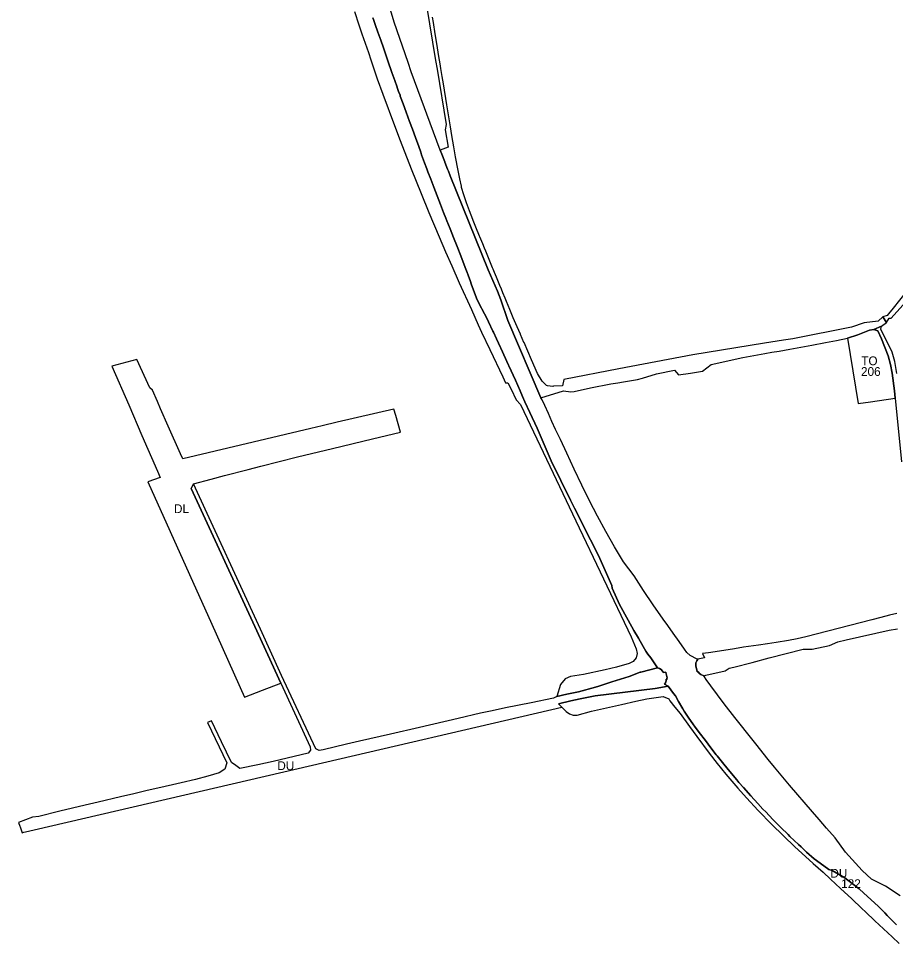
# Model space of a CAD drawing. Extents: x -521047 to -518054, y -1194945 to -1189555.
# Drawn here: x -521047 to -520050, y -1192673 to -1191621 of the extents above; entities that cross this region are included whole.
import ezdxf

# ---------------------------------------------------------------- set-up
doc = ezdxf.new("R2010")
doc.units = 0
for name, color, linetype in [('90310013', 7, 'Continuous'), ('90310023', 7, 'Continuous'), ('90320013', 7, 'Continuous'), ('90340013', 7, 'Continuous'), ('90430023', 7, 'Continuous'), ('90450013', 7, 'Continuous'), ('ID_navrh', 7, 'Continuous')]:
    doc.layers.add(name, color=color, linetype=linetype)

msp = doc.modelspace()

# ---------------------------------------------------------------- linework, layer by layer
at = {"layer": '90310013'}
for points in [[(-520583.24, -1191606.18), (-520572.92, -1191668.76), (-520571.31, -1191678.64), (-520560.94, -1191741.4), (-520562, -1191747.31), (-520558.71, -1191767.21), (-520567.63, -1191770.59), (-520565.86, -1191775.32), (-520562.43, -1191784.06), (-520562.29, -1191784.41), (-520559.25, -1191792.33), (-520558.35, -1191794.67), (-520556.42, -1191799.88), (-520513.1, -1191906.77), (-520502.57, -1191931.05), (-520498.81, -1191940.91), (-520490.89, -1191964.3), (-520453.11, -1192052.05), (-520427.58, -1192044.36), (-520419.12, -1192045.34), (-520415.23, -1192044.95), (-520396.61, -1192040.92), (-520373.61, -1192036.43), (-520365.78, -1192035.12), (-520359.07, -1192034), (-520343.38, -1192031.33), (-520337.55, -1192029.72), (-520321.68, -1192025.09), (-520301.24, -1192020.66), (-520296.64, -1192026.13), (-520282.86, -1192024.02), (-520269.44, -1192022.05), (-520259.31, -1192014.22), (-520223.56, -1192006.45), (-520211.03, -1192004.19), (-520198.5, -1192001.91), (-520190.36, -1192000.43), (-520182.23, -1191998.96), (-520169.8, -1191996.69), (-520157.4, -1191994.44), (-520144.97, -1191992.17), (-520129.2, -1191989.31), (-520116.89, -1191987.05), (-520104.53, -1191984.27), (-520092.41, -1191980.61), (-520079.34, -1191975.35), (-520074.25, -1191974.62), (-520065.72, -1191970.89), (-520060.15, -1191966.67), (-520064.17, -1191960.26), (-520069.51, -1191964.99), (-520085.46, -1191967.04), (-520099.84, -1191971.93), (-520166.67, -1191985.2), (-520177.25, -1191986.81), (-520198.94, -1191990.1), (-520280.31, -1192003.2), (-520364.5, -1192019.1), (-520426.95, -1192031.34)], [(-520426.95, -1192031.34), (-520428.58, -1192038.61), (-520438.66, -1192038.99), (-520439.75, -1192039.45), (-520445.83, -1192038.53), (-520446.9, -1192038.37), (-520451.84, -1192033.1), (-520456.96, -1192024.37), (-520463.71, -1192009.09), (-520472.36, -1191989.33), (-520472.43, -1191989.16), (-520476.27, -1191980.29), (-520476.54, -1191979.67), (-520480.14, -1191971.36), (-520484.6, -1191961.08), (-520488.52, -1191951.69), (-520492.29, -1191942.67), (-520492.35, -1191942.53), (-520493.89, -1191938.79), (-520496.32, -1191932.89), (-520498, -1191928.82), (-520499.82, -1191924.41), (-520501.41, -1191920.55), (-520503.68, -1191914.99), (-520505.77, -1191909.89), (-520507.4, -1191905.91), (-520508.05, -1191904.38), (-520515.15, -1191887.48), (-520515.96, -1191885.49), (-520517.43, -1191881.88), (-520519.36, -1191877.12), (-520522.68, -1191868.97), (-520522.92, -1191868.36), (-520527.05, -1191858.16), (-520530.18, -1191850.44), (-520530.55, -1191849.48), (-520534.33, -1191839.76), (-520537.93, -1191830.32), (-520540.91, -1191821.42), (-520543.32, -1191813.06), (-520543.6, -1191811.69), (-520545.36, -1191803.05), (-520547.27, -1191793.71), (-520550.3, -1191778.29), (-520552.16, -1191767), (-520554.32, -1191753.79), (-520555.95, -1191744), (-520557.81, -1191732.77), (-520560.08, -1191719.1), (-520564, -1191695.24), (-520565.37, -1191686.86), (-520566.91, -1191677.66), (-520567.79, -1191672.26), (-520569.19, -1191663.93), (-520571.57, -1191649.5), (-520573.38, -1191638.42), (-520575.51, -1191625.38), (-520576.48, -1191619.53)], [(-520048.04, -1192024.54), (-520050.49, -1192010.79), (-520053.59, -1192000.14), (-520066.59, -1191973.96), (-520065.72, -1191970.89), (-520074.25, -1191974.62), (-520069.93, -1191975.99), (-520065.48, -1191985.04), (-520058.25, -1192004.27), (-520055.59, -1192014.2), (-520053.58, -1192024.28), (-520050.85, -1192044.4), (-520050, -1192052.77), (-520042.86, -1192124.96)], [(-520308.29, -1192379.91), (-520312.6, -1192377.77), (-520311.52, -1192376.37), (-520310.68, -1192374.15), (-520310.56, -1192372.14), (-520309.5, -1192371.9), (-520309.71, -1192370.96), (-520309.59, -1192370.62), (-520310.97, -1192364.44), (-520311.06, -1192364.05), (-520313.84, -1192364.68), (-520314.84, -1192362.92), (-520316.29, -1192361.16), (-520318.16, -1192359.98), (-520320.4, -1192359.14), (-520339.38, -1192363.97), (-520340.17, -1192364.16), (-520352.73, -1192368.93), (-520372.47, -1192375.28), (-520387.37, -1192380.02), (-520390.99, -1192381.17), (-520410.3, -1192386.31), (-520423.63, -1192389.27), (-520435.18, -1192391.83), (-520438.72, -1192393.79), (-520464.05, -1192398.85), (-520493.5, -1192404.76), (-520508.74, -1192407.91), (-520521.69, -1192410.69), (-520547.23, -1192416.63), (-520591.42, -1192426.87), (-520624.25, -1192434.52), (-520659.49, -1192442.68), (-520674.16, -1192446.1), (-520700.9, -1192452.29), (-520705.38, -1192453.34), (-520709.22, -1192451.33), (-520748.17, -1192367.77), (-520772.3, -1192315.26), (-520848.21, -1192150.07), (-520851.18, -1192155.31), (-520778.66, -1192312.37), (-520749.03, -1192376.55), (-520715.58, -1192448.99), (-520715.38, -1192452.8), (-520717.93, -1192456.26), (-520757.59, -1192465.66), (-520775.03, -1192469.66), (-520795.54, -1192473.81), (-520800.34, -1192470.38), (-520805.14, -1192466.95), (-520816.49, -1192443.18), (-520827.84, -1192419.41), (-520832.42, -1192421.41), (-520810.52, -1192467.28), (-520812.86, -1192474.26), (-520819, -1192478.55), (-520831.91, -1192482.32), (-520846.11, -1192486.03), (-520862.36, -1192489.81), (-520867.3, -1192490.96), (-520885.36, -1192495.15), (-520901.21, -1192498.82), (-520916.4, -1192502.38), (-520931.25, -1192505.82), (-520956.94, -1192511.77), (-520971.48, -1192515.16), (-521000.32, -1192522.3), (-521024.31, -1192528.23), (-521031.5, -1192528.93), (-521047.48, -1192534.92), (-521045.8, -1192539.12), (-521045.42, -1192540.08), (-521043.45, -1192546.66), (-521041.54, -1192546.21), (-521039.64, -1192545.77), (-521034.64, -1192544.61), (-521029.64, -1192543.45), (-520729.45, -1192473.76), (-520429.27, -1192404.08), (-520433.25, -1192400.13), (-520419.21, -1192396.83), (-520408.52, -1192394.32), (-520391.27, -1192391.06), (-520323, -1192382.65), (-520308.29, -1192379.91)], [(-520048.15, -1192297.25), (-520056.72, -1192299.47), (-520066.54, -1192302), (-520076.52, -1192304.58), (-520151.67, -1192323.97), (-520161.54, -1192326.38), (-520171.64, -1192328.13), (-520185.37, -1192330.24), (-520195.42, -1192331.76), (-520205.45, -1192333.29), (-520222.7, -1192335.85), (-520232.72, -1192337.5), (-520254.9, -1192340.88), (-520262.42, -1192342.12), (-520269.2, -1192343.04), (-520267.02, -1192347.71), (-520274.54, -1192349.23), (-520275.84, -1192351.17), (-520276.91, -1192353.53), (-520277.02, -1192356.01), (-520276.82, -1192356.91), (-520275.37, -1192363.33), (-520275.24, -1192363.9), (-520274.14, -1192363.66), (-520272.78, -1192365.55), (-520271.03, -1192366.84), (-520267.65, -1192368.23)], [(-520267.65, -1192368.23), (-520265.64, -1192367.66), (-520243.36, -1192362.72), (-520238.84, -1192359.64), (-520233.56, -1192358.34), (-520212.74, -1192353.2), (-520193.4, -1192348.01), (-520174.07, -1192342.77), (-520154.82, -1192337.98), (-520144.55, -1192338.08), (-520124.86, -1192333.87), (-520115.51, -1192329.52), (-520105.95, -1192327.26), (-520057.05, -1192316.46), (-520047.46, -1192314.76)]]:
    msp.add_lwpolyline(points, dxfattribs=at)
at = {"layer": '90310023'}
for points in [[(-520665.33, -1191613.04), (-520660.4, -1191628.12), (-520656.86, -1191638.41), (-520649.42, -1191659.64), (-520646.67, -1191667.99), (-520639.25, -1191689.54), (-520632.82, -1191707.09), (-520619.58, -1191742.71), (-520613.34, -1191759.5), (-520600.61, -1191791.87), (-520589.45, -1191820.06), (-520580.78, -1191841.33), (-520568.92, -1191869.32), (-520561.8, -1191886.19), (-520554.58, -1191902.23), (-520545.99, -1191921.37), (-520532.26, -1191951.92), (-520524.4, -1191969.39), (-520520.62, -1191977.39), (-520511.32, -1191997.09), (-520496.63, -1192028.24), (-520493.41, -1192035.03), (-520490.69, -1192035.01), (-520487.08, -1192042.46), (-520481.41, -1192054.32), (-520476.52, -1192059.92), (-520413.24, -1192192.22), (-520350.34, -1192323.78), (-520344.77, -1192337.74), (-520343.61, -1192342.88), (-520344.8, -1192347.99), (-520348.08, -1192352.07), (-520352.85, -1192354.32), (-520367.27, -1192358.55), (-520379.97, -1192361.36), (-520404.73, -1192366.86), (-520419.59, -1192369.13), (-520425.51, -1192371.59), (-520430.97, -1192378.16), (-520435.18, -1192391.83), (-520423.63, -1192389.27), (-520410.3, -1192386.31), (-520390.99, -1192381.17), (-520387.37, -1192380.02), (-520372.47, -1192375.28), (-520352.73, -1192368.93), (-520340.17, -1192364.16), (-520339.38, -1192363.97), (-520320.4, -1192359.14), (-520325.1, -1192352.46), (-520328.24, -1192347.97), (-520331.36, -1192343.58), (-520333.65, -1192340.33), (-520336.81, -1192334.84), (-520342.29, -1192325.3), (-520347.31, -1192316.58), (-520353.88, -1192305.15), (-520363.69, -1192287.06), (-520371.94, -1192268.45), (-520372.29, -1192265.77), (-520387.63, -1192231.6), (-520396.88, -1192213.72), (-520414.93, -1192177.76), (-520419.64, -1192168.56), (-520441.55, -1192123.72), (-520449.56, -1192105.3), (-520457.37, -1192086.83), (-520465.86, -1192068.71), (-520471.3, -1192056.68), (-520474.06, -1192050.59), (-520476.86, -1192044.07), (-520482.01, -1192032.05), (-520489.78, -1192015.99), (-520490.14, -1192015.17), (-520498.74, -1191995.62), (-520499.13, -1191994.79), (-520503.53, -1191985.28), (-520507.16, -1191977.44), (-520507.66, -1191976.43), (-520512.79, -1191965.9), (-520515.96, -1191959.4), (-520517.18, -1191956.82), (-520523.93, -1191944.46), (-520526.29, -1191938.72), (-520532.31, -1191922.75), (-520533.39, -1191919.77), (-520535.87, -1191912.92), (-520537.01, -1191909.76), (-520539.14, -1191903.88), (-520544.3, -1191890.84), (-520548.49, -1191880.24), (-520552.5, -1191870.05), (-520556.46, -1191860.17), (-520560.11, -1191851.11), (-520561.36, -1191848.01), (-520563.85, -1191841.56), (-520567.46, -1191832.2), (-520571.18, -1191822.61), (-520574.96, -1191812.85), (-520578.48, -1191803.63), (-520581.71, -1191795.12), (-520582.94, -1191791.88), (-520585.49, -1191784.87), (-520588.8, -1191775.76), (-520589.8, -1191773.03), (-520592.13, -1191766.51), (-520595.79, -1191756.32), (-520599.31, -1191746.66), (-520602.48, -1191737.99), (-520606.37, -1191727.43), (-520609.95, -1191717.76), (-520613.08, -1191709.13), (-520613.42, -1191708.19), (-520614.97, -1191703.91), (-520616.56, -1191699.54), (-520616.79, -1191698.9), (-520619.43, -1191691.52), (-520622.73, -1191682.3), (-520623.96, -1191678.84), (-520626.06, -1191672.54), (-520629.16, -1191663.22), (-520629.49, -1191662.22), (-520632.32, -1191654.19), (-520635.33, -1191645.63), (-520638.56, -1191636.54), (-520641.71, -1191627.72), (-520643.73, -1191622.06), (-520644.52, -1191620)], [(-520308.29, -1192379.91), (-520323, -1192382.65), (-520391.27, -1192391.06), (-520408.52, -1192394.32), (-520419.21, -1192396.83), (-520433.25, -1192400.13), (-520429.27, -1192404.08), (-520424.5, -1192408.81), (-520420.44, -1192411.62), (-520416.34, -1192412.93), (-520412.04, -1192413.12), (-520395.48, -1192408.42), (-520361.57, -1192400.9), (-520345.17, -1192397.26), (-520332.75, -1192394.51), (-520314.08, -1192391.89), (-520307.78, -1192394.28), (-520306.33, -1192396.84), (-520300.6, -1192403.76), (-520294.74, -1192411.1), (-520284.01, -1192425.9), (-520275.92, -1192437.11), (-520261.71, -1192456.26), (-520252.63, -1192468), (-520242.91, -1192479.92), (-520229.16, -1192496.14), (-520219.35, -1192507.19), (-520206.14, -1192521.43), (-520190.54, -1192537.37), (-520164.14, -1192562.58), (-520156.21, -1192570), (-520143.43, -1192581.71), (-520132.06, -1192591.63), (-520123.66, -1192599.39), (-520112.32, -1192610.16), (-520099.47, -1192621.84), (-520088.02, -1192632.83), (-520083.77, -1192636.81), (-520073.19, -1192646.74), (-520053.58, -1192665.11), (-520045.5, -1192672.63)], [(-520048.69, -1192651.55), (-520055.38, -1192644.58), (-520059.17, -1192640.62), (-520061.83, -1192637.85), (-520068.05, -1192631.68), (-520069.09, -1192630.69), (-520077.92, -1192622.6), (-520085.81, -1192615.47), (-520091.18, -1192610.64), (-520094.08, -1192608.35), (-520107.21, -1192597.98), (-520121.95, -1192589.69), (-520125.41, -1192588.44), (-520139.68, -1192578.29), (-520142.13, -1192576.55), (-520150.82, -1192568.64), (-520157.19, -1192562.84), (-520159.9, -1192560.25), (-520169.79, -1192550.8), (-520171.93, -1192548.76), (-520180.03, -1192540.77), (-520186.45, -1192534.45), (-520189.15, -1192531.64), (-520197.42, -1192523.04), (-520200.54, -1192519.8), (-520206.32, -1192513.55), (-520214.38, -1192504.82), (-520222.74, -1192495.39), (-520227.93, -1192489.55), (-520230.36, -1192486.59), (-520238.03, -1192477.24), (-520245.01, -1192468.75), (-520252.72, -1192459.36), (-520253.78, -1192458.07), (-520259.81, -1192450.1), (-520266.04, -1192441.85), (-520273.06, -1192432.56), (-520278.33, -1192425.59), (-520279.48, -1192423.96), (-520285.5, -1192415.41), (-520290.27, -1192408.65), (-520291.84, -1192405.87), (-520296.67, -1192397.37), (-520300.19, -1192391.16), (-520302.3, -1192388.23), (-520308.29, -1192379.91)]]:
    msp.add_lwpolyline(points, dxfattribs=at)
at = {"layer": '90320013'}
for points in [[(-520044.56, -1192618.55), (-520061.16, -1192607.27), (-520076.96, -1192599.48), (-520087.56, -1192589.6), (-520106.61, -1192568.96), (-520118.39, -1192552.66), (-520128.18, -1192541.53), (-520136.69, -1192531.64), (-520144.14, -1192523.08), (-520170.22, -1192492.58), (-520187.51, -1192472.01), (-520194.58, -1192463.28), (-520208.64, -1192445.57), (-520211.73, -1192441.71), (-520232.33, -1192415.78), (-520244.47, -1192400.09), (-520259.75, -1192379.49), (-520264.96, -1192372.31), (-520267.03, -1192369.46), (-520267.65, -1192368.23), (-520271.03, -1192366.84), (-520272.78, -1192365.55), (-520274.14, -1192363.66), (-520275.24, -1192363.9), (-520275.37, -1192363.33), (-520276.82, -1192356.91), (-520277.02, -1192356.01), (-520276.91, -1192353.53), (-520275.84, -1192351.17), (-520274.54, -1192349.23), (-520275.44, -1192349.46), (-520283.19, -1192345.02), (-520287.05, -1192341.84), (-520289.68, -1192338.14), (-520295.99, -1192329.24), (-520302.69, -1192319.77), (-520308.83, -1192311.12), (-520313.94, -1192303.92), (-520325.37, -1192287.72), (-520336.34, -1192271.22), (-520347.07, -1192254.47), (-520359.31, -1192238.71), (-520369.38, -1192221.59), (-520379.14, -1192204.29), (-520388.67, -1192186.84), (-520397.97, -1192169.26), (-520406.75, -1192151.4), (-520415.17, -1192133.35), (-520423.57, -1192115.27), (-520430.99, -1192099.66), (-520436.41, -1192088.25), (-520440.7, -1192079.25), (-520444.67, -1192070.07), (-520448.65, -1192060.89), (-520451.85, -1192054.55), (-520452.5, -1192053.26), (-520453.11, -1192052.05), (-520490.89, -1191964.3), (-520498.81, -1191940.91), (-520502.57, -1191931.05), (-520513.1, -1191906.77), (-520556.42, -1191799.88), (-520558.35, -1191794.67), (-520559.25, -1191792.33), (-520562.29, -1191784.41), (-520562.43, -1191784.06), (-520565.86, -1191775.32), (-520567.63, -1191770.59), (-520600.77, -1191681.45), (-520604.04, -1191671.07), (-520620.11, -1191625.25), (-520624.44, -1191610.86)], [(-520644.52, -1191620), (-520643.73, -1191622.06), (-520641.71, -1191627.72), (-520638.56, -1191636.54), (-520635.33, -1191645.63), (-520632.32, -1191654.19), (-520629.49, -1191662.22), (-520629.16, -1191663.22), (-520626.06, -1191672.54), (-520623.96, -1191678.84), (-520622.73, -1191682.3), (-520619.43, -1191691.52), (-520616.79, -1191698.9), (-520616.56, -1191699.54), (-520614.97, -1191703.91), (-520613.42, -1191708.19), (-520613.08, -1191709.13), (-520609.95, -1191717.76), (-520606.37, -1191727.43), (-520602.48, -1191737.99), (-520599.31, -1191746.66), (-520595.79, -1191756.32), (-520592.13, -1191766.51), (-520589.8, -1191773.03), (-520588.8, -1191775.76), (-520585.49, -1191784.87), (-520582.94, -1191791.88), (-520581.71, -1191795.12), (-520578.48, -1191803.63), (-520574.96, -1191812.85), (-520571.18, -1191822.61), (-520567.46, -1191832.2), (-520563.85, -1191841.56), (-520561.36, -1191848.01), (-520560.11, -1191851.11), (-520556.46, -1191860.17), (-520552.5, -1191870.05), (-520548.49, -1191880.24), (-520544.3, -1191890.84), (-520539.14, -1191903.88), (-520537.01, -1191909.76), (-520535.87, -1191912.92), (-520533.39, -1191919.77), (-520532.31, -1191922.75), (-520526.29, -1191938.72), (-520523.93, -1191944.46), (-520517.18, -1191956.82), (-520515.96, -1191959.4), (-520512.79, -1191965.9), (-520507.66, -1191976.43), (-520507.16, -1191977.44), (-520503.53, -1191985.28), (-520499.13, -1191994.79), (-520498.74, -1191995.62), (-520490.14, -1192015.17), (-520489.78, -1192015.99), (-520482.01, -1192032.05), (-520476.86, -1192044.07), (-520474.06, -1192050.59), (-520471.3, -1192056.68), (-520465.86, -1192068.71), (-520457.37, -1192086.83), (-520449.56, -1192105.3), (-520441.55, -1192123.72), (-520419.64, -1192168.56), (-520414.93, -1192177.76), (-520396.88, -1192213.72), (-520387.63, -1192231.6), (-520372.29, -1192265.77), (-520371.94, -1192268.45), (-520363.69, -1192287.06), (-520353.88, -1192305.15), (-520347.31, -1192316.58), (-520342.29, -1192325.3), (-520336.81, -1192334.84), (-520333.65, -1192340.33), (-520331.36, -1192343.58), (-520328.24, -1192347.97), (-520325.1, -1192352.46), (-520320.4, -1192359.14), (-520318.16, -1192359.98), (-520316.29, -1192361.16), (-520314.84, -1192362.92), (-520313.84, -1192364.68), (-520311.06, -1192364.05), (-520310.97, -1192364.44), (-520309.59, -1192370.62), (-520309.71, -1192370.96), (-520309.5, -1192371.9), (-520310.56, -1192372.14), (-520310.68, -1192374.15), (-520311.52, -1192376.37), (-520312.6, -1192377.77), (-520308.29, -1192379.91), (-520302.3, -1192388.23), (-520300.19, -1192391.16), (-520296.67, -1192397.37), (-520291.84, -1192405.87), (-520290.27, -1192408.65), (-520285.5, -1192415.41), (-520279.48, -1192423.96), (-520278.33, -1192425.59), (-520273.06, -1192432.56), (-520266.04, -1192441.85), (-520259.81, -1192450.1), (-520253.78, -1192458.07), (-520252.72, -1192459.36), (-520245.01, -1192468.75), (-520238.03, -1192477.24), (-520230.36, -1192486.59), (-520227.93, -1192489.55), (-520222.74, -1192495.39), (-520214.38, -1192504.82), (-520206.32, -1192513.55), (-520200.54, -1192519.8), (-520197.42, -1192523.04), (-520189.15, -1192531.64), (-520186.45, -1192534.45), (-520180.03, -1192540.77), (-520171.93, -1192548.76), (-520169.79, -1192550.8), (-520159.9, -1192560.25), (-520157.19, -1192562.84), (-520150.82, -1192568.64), (-520142.13, -1192576.55), (-520139.68, -1192578.29), (-520125.41, -1192588.44), (-520121.95, -1192589.69), (-520107.21, -1192597.98), (-520094.08, -1192608.35), (-520091.18, -1192610.64), (-520085.81, -1192615.47), (-520077.92, -1192622.6), (-520069.09, -1192630.69), (-520068.05, -1192631.68), (-520061.83, -1192637.85), (-520059.17, -1192640.62), (-520055.38, -1192644.58), (-520048.69, -1192651.55)]]:
    msp.add_lwpolyline(points, dxfattribs=at)
at = {"layer": '90340013'}
msp.add_lwpolyline([(-520618.37, -1192072.35), (-520620.5, -1192064.91), (-520684.93, -1192080.06), (-520701.85, -1192084.04), (-520715.06, -1192087.15), (-520860.7, -1192121.39), (-520863.21, -1192115.71), (-520877.05, -1192084.34), (-520885.79, -1192064.54), (-520889.36, -1192056.46), (-520895.11, -1192043.42), (-520898.22, -1192040.98), (-520912.71, -1192008.61), (-520941.16, -1192016.12), (-520921.91, -1192060.3), (-520907.04, -1192095.09), (-520889.52, -1192135.58), (-520886.27, -1192142.96), (-520900.27, -1192147.67), (-520827.64, -1192309.54), (-520790.38, -1192392.59), (-520790.37, -1192392.59), (-520769.7, -1192384.57), (-520749.03, -1192376.55), (-520778.66, -1192312.37), (-520851.18, -1192155.31), (-520848.21, -1192150.07), (-520828.27, -1192144.69), (-520813.01, -1192140.6), (-520786.26, -1192133.58), (-520771.74, -1192129.79), (-520729.94, -1192119.3), (-520690.33, -1192109.89), (-520644.57, -1192098.88), (-520612.97, -1192091.26), (-520615.67, -1192081.81), (-520618.37, -1192072.35)], dxfattribs=at)
at = {"layer": '90430023'}
msp.add_lwpolyline([(-520104.53, -1191984.27), (-520092.32, -1192058.51), (-520078.17, -1192056.59), (-520050, -1192052.77), (-520050.85, -1192044.4), (-520053.58, -1192024.28), (-520055.59, -1192014.2), (-520058.25, -1192004.27), (-520065.48, -1191985.04), (-520069.93, -1191975.99), (-520074.25, -1191974.62), (-520079.34, -1191975.35), (-520092.41, -1191980.61), (-520104.53, -1191984.27)], dxfattribs=at)
at = {"layer": '90450013'}
msp.add_lwpolyline([(-520055.94, -1191954.58), (-520056.08, -1191954.75), (-520059.24, -1191958.73), (-520064.17, -1191960.26), (-520060.15, -1191966.67), (-520056.79, -1191961.78), (-520054.76, -1191961.68), (-520027.63, -1191931.83), (-520000.5, -1191901.98), (-520005.16, -1191895.35), (-520007.5, -1191891.48), (-520019.56, -1191819.22), (-520018.47, -1191812.73), (-520016.05, -1191807.34), (-520032.53, -1191806.97), (-520029.72, -1191820.71), (-520027.04, -1191833.79), (-520014.4, -1191893.4), (-520008.2, -1191898.59), (-520015.01, -1191905.83), (-520030.81, -1191922.99), (-520052.53, -1191950.29), (-520055.94, -1191954.58)], dxfattribs=at)

# ---------------------------------------------------------------- texts
at = {"layer": '90310013'}
msp.add_text('DU', height=10, rotation=0, dxfattribs=at).set_placement((-520753.02, -1192475.49))
at = {"layer": '90310023'}
msp.add_text('DU', height=10, rotation=360, dxfattribs=at).set_placement((-520123.82, -1192597.75))
at = {"layer": '90340013'}
msp.add_text('DL', height=10, rotation=360, dxfattribs=at).set_placement((-520870.58, -1192183.29))
at = {"layer": '90430023'}
msp.add_text('TO', height=10, rotation=360, dxfattribs=at).set_placement((-520088.68, -1192015.11))
at = {"layer": 'ID_navrh'}
for s, p in [('206', (-520088.96, -1192027.3)), ('122', (-520111.52, -1192609.62))]:
    msp.add_text(s, height=10, rotation=0, dxfattribs=at).set_placement(p)

doc.saveas('drawing.dxf')
